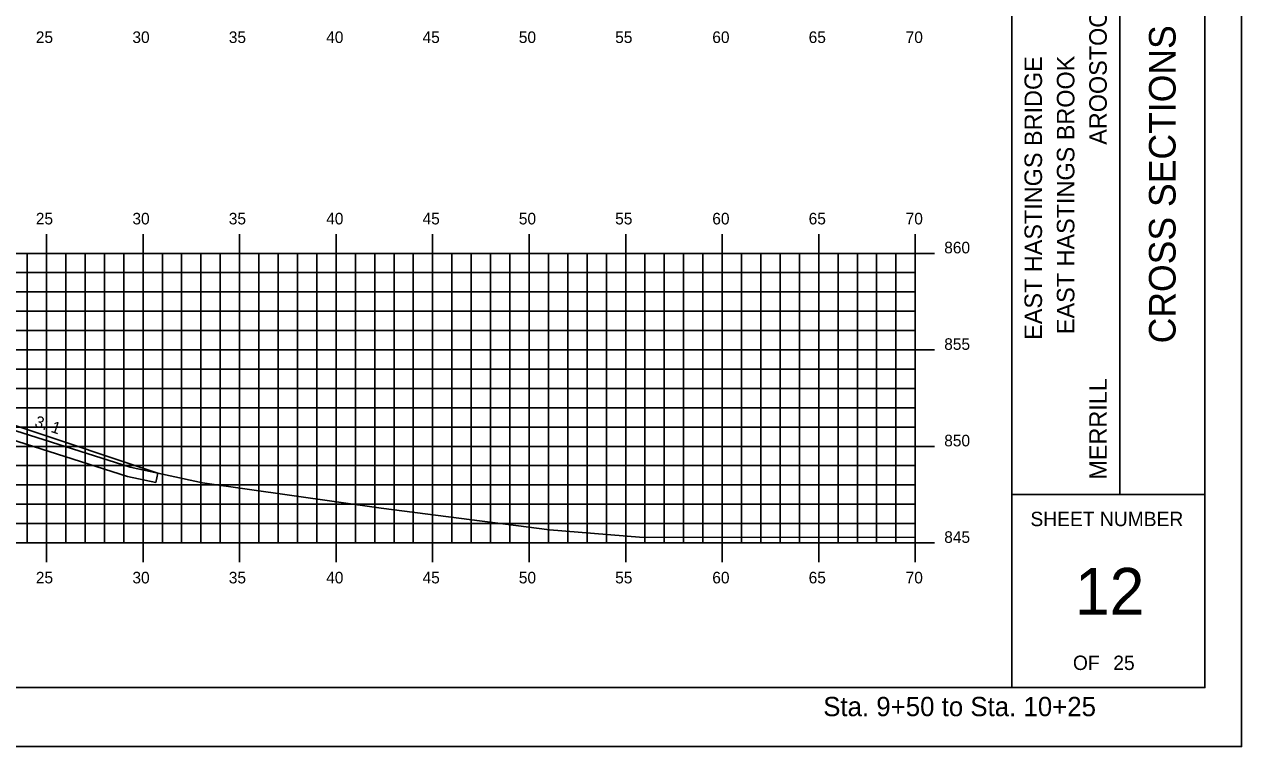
# Model space of a CAD drawing. Extents: x 2194738 to 2195190, y 863888 to 863998.
# Drawn here: x 2194944.1 to 2195007.2, y 863888.4 to 863925.8 of the extents above; entities that cross this region are included whole.
import ezdxf

# ---------------------------------------------------------------- set-up
doc = ezdxf.new("R2010")
doc.units = 0
for name, color, linetype in [('ANNOTATION', 7, 'Continuous'), ('BORDER', 7, 'Continuous'), ('BRIDGE_TITLE', 7, 'Continuous'), ('H_V ANNOTATION', 7, 'Continuous'), ('MAJOR', 7, 'Continuous'), ('MINOR', 7, 'Continuous'), ('PLOT BOUNDARY', 7, 'Continuous'), ('S_Roadway_Centerline', 7, 'Continuous'), ('TEMPLATE', 7, 'Continuous')]:
    doc.layers.add(name, color=color, linetype=linetype)

msp = doc.modelspace()

# ---------------------------------------------------------------- linework, layer by layer
at = {"layer": 'BORDER'}
for p, q in [((2194995.256, 863891.446), (2194995.256, 863996.446)), ((2195000.847, 863901.449), (2195000.847, 863936.449)), ((2194995.256, 863901.449), (2195005.256, 863901.449))]:
    msp.add_line(p, q, dxfattribs=at)
msp.add_lwpolyline([(2194845.256, 863891.446), (2195005.256, 863891.446), (2195005.256, 863996.446), (2194845.256, 863996.446)], close=True, dxfattribs=at)
at = {"layer": 'MAJOR'}
for p, q in [((2194945.256, 863914.948), (2194945.256, 863913.946)), ((2194950.256, 863914.948), (2194950.256, 863913.946)), ((2194955.256, 863914.948), (2194955.256, 863913.946)), ((2194960.256, 863914.948), (2194960.256, 863913.946)), ((2194965.256, 863914.948), (2194965.256, 863913.946)), ((2194970.256, 863914.948), (2194970.256, 863913.946)), ((2194975.256, 863914.948), (2194975.256, 863913.946)), ((2194980.256, 863914.948), (2194980.256, 863913.946)), ((2194985.256, 863914.948), (2194985.256, 863913.946)), ((2194990.256, 863914.948), (2194990.256, 863913.946)), ((2194850.256, 863913.946), (2194990.256, 863913.946)), ((2194850.256, 863913.946), (2194990.256, 863913.946)), ((2194945.256, 863898.946), (2194945.256, 863913.946)), ((2194950.256, 863898.946), (2194950.256, 863913.946)), ((2194955.256, 863898.946), (2194955.256, 863913.946)), ((2194960.256, 863898.946), (2194960.256, 863913.946)), ((2194965.256, 863898.946), (2194965.256, 863913.946)), ((2194970.256, 863898.946), (2194970.256, 863913.946)), ((2194975.256, 863898.946), (2194975.256, 863913.946)), ((2194980.256, 863898.946), (2194980.256, 863913.946)), ((2194985.256, 863898.946), (2194985.256, 863913.946)), ((2194991.258, 863913.946), (2194989.254, 863913.946)), ((2194990.256, 863898.946), (2194990.256, 863913.946)), ((2194990.256, 863898.946), (2194990.256, 863913.946)), ((2194850.256, 863908.946), (2194990.256, 863908.946)), ((2194991.258, 863908.946), (2194989.254, 863908.946)), ((2194850.256, 863903.946), (2194990.256, 863903.946)), ((2194991.258, 863903.946), (2194989.254, 863903.946)), ((2194850.256, 863898.946), (2194990.256, 863898.946)), ((2194945.256, 863897.944), (2194945.256, 863898.946)), ((2194950.256, 863897.944), (2194950.256, 863898.946)), ((2194955.256, 863897.944), (2194955.256, 863898.946)), ((2194960.256, 863897.944), (2194960.256, 863898.946)), ((2194965.256, 863897.944), (2194965.256, 863898.946)), ((2194970.256, 863897.944), (2194970.256, 863898.946)), ((2194975.256, 863897.944), (2194975.256, 863898.946)), ((2194980.256, 863897.944), (2194980.256, 863898.946)), ((2194985.256, 863897.944), (2194985.256, 863898.946)), ((2194991.258, 863898.946), (2194989.254, 863898.946)), ((2194990.256, 863897.944), (2194990.256, 863898.946))]:
    msp.add_line(p, q, dxfattribs=at)
at = {"layer": 'MINOR'}
for p, q in [((2194944.256, 863898.946), (2194944.256, 863913.946)), ((2194946.256, 863898.946), (2194946.256, 863913.946)), ((2194947.256, 863898.946), (2194947.256, 863913.946)), ((2194948.256, 863898.946), (2194948.256, 863913.946)), ((2194949.256, 863898.946), (2194949.256, 863913.946)), ((2194951.256, 863898.946), (2194951.256, 863913.946)), ((2194952.256, 863898.946), (2194952.256, 863913.946)), ((2194953.256, 863898.946), (2194953.256, 863913.946)), ((2194954.256, 863898.946), (2194954.256, 863913.946)), ((2194956.256, 863898.946), (2194956.256, 863913.946)), ((2194957.256, 863898.946), (2194957.256, 863913.946)), ((2194958.256, 863898.946), (2194958.256, 863913.946)), ((2194959.256, 863898.946), (2194959.256, 863913.946)), ((2194961.256, 863898.946), (2194961.256, 863913.946)), ((2194962.256, 863898.946), (2194962.256, 863913.946)), ((2194963.256, 863898.946), (2194963.256, 863913.946)), ((2194964.256, 863898.946), (2194964.256, 863913.946)), ((2194966.256, 863898.946), (2194966.256, 863913.946)), ((2194967.256, 863898.946), (2194967.256, 863913.946)), ((2194968.256, 863898.946), (2194968.256, 863913.946)), ((2194969.256, 863898.946), (2194969.256, 863913.946)), ((2194971.256, 863898.946), (2194971.256, 863913.946)), ((2194972.256, 863898.946), (2194972.256, 863913.946)), ((2194973.256, 863898.946), (2194973.256, 863913.946)), ((2194974.256, 863898.946), (2194974.256, 863913.946)), ((2194976.256, 863898.946), (2194976.256, 863913.946)), ((2194977.256, 863898.946), (2194977.256, 863913.946)), ((2194978.256, 863898.946), (2194978.256, 863913.946)), ((2194979.256, 863898.946), (2194979.256, 863913.946)), ((2194981.256, 863898.946), (2194981.256, 863913.946)), ((2194982.256, 863898.946), (2194982.256, 863913.946)), ((2194983.256, 863898.946), (2194983.256, 863913.946)), ((2194984.256, 863898.946), (2194984.256, 863913.946)), ((2194986.256, 863898.946), (2194986.256, 863913.946)), ((2194987.256, 863898.946), (2194987.256, 863913.946)), ((2194988.256, 863898.946), (2194988.256, 863913.946)), ((2194989.256, 863898.946), (2194989.256, 863913.946)), ((2194850.256, 863912.946), (2194990.256, 863912.946)), ((2194990.256, 863912.946), (2194989.254, 863912.946)), ((2194850.256, 863911.946), (2194990.256, 863911.946)), ((2194990.256, 863911.946), (2194989.254, 863911.946)), ((2194850.256, 863910.946), (2194990.256, 863910.946)), ((2194990.256, 863910.946), (2194989.254, 863910.946)), ((2194850.256, 863909.946), (2194990.256, 863909.946)), ((2194990.256, 863909.946), (2194989.254, 863909.946)), ((2194850.256, 863907.946), (2194990.256, 863907.946)), ((2194990.256, 863907.946), (2194989.254, 863907.946)), ((2194850.256, 863906.946), (2194990.256, 863906.946)), ((2194990.256, 863906.946), (2194989.254, 863906.946)), ((2194850.256, 863905.946), (2194990.256, 863905.946)), ((2194990.256, 863905.946), (2194989.254, 863905.946)), ((2194850.256, 863904.946), (2194990.256, 863904.946)), ((2194990.256, 863904.946), (2194989.254, 863904.946)), ((2194850.256, 863902.946), (2194990.256, 863902.946)), ((2194990.256, 863902.946), (2194989.254, 863902.946)), ((2194850.256, 863901.946), (2194990.256, 863901.946)), ((2194990.256, 863901.946), (2194989.254, 863901.946)), ((2194850.256, 863900.946), (2194990.256, 863900.946)), ((2194990.256, 863900.946), (2194989.254, 863900.946)), ((2194850.256, 863899.946), (2194990.256, 863899.946)), ((2194990.256, 863899.946), (2194989.254, 863899.946))]:
    msp.add_line(p, q, dxfattribs=at)
at = {"layer": 'PLOT BOUNDARY'}
msp.add_lwpolyline([(2194837.163, 863888.387), (2195007.163, 863888.387), (2195007.163, 863998.387), (2194837.163, 863998.387)], close=True, dxfattribs=at)
at = {"layer": 'S_Roadway_Centerline'}
msp.add_lwpolyline([(2194850.256, 863903.946), (2194862.163, 863904.928), (2194876.641, 863904.659), (2194888.683, 863904.484), (2194891.949, 863905.503), (2194896.37, 863906.93), (2194900.004, 863907.039), (2194904.289, 863907.129), (2194905.874, 863907.236), (2194908.794, 863907.591), (2194913.318, 863907.695), (2194920.296, 863907.807), (2194927.306, 863907.711), (2194931.88, 863907.66), (2194933.306, 863907.572), (2194934.219, 863907.522), (2194935.131, 863907.329), (2194936.586, 863906.993), (2194949.583, 863902.874), (2194953.328, 863902.06), (2194962.598, 863900.741), (2194971.313, 863899.617), (2194975.97, 863899.247), (2194990.256, 863899.22)], dxfattribs=at)
at = {"layer": 'TEMPLATE'}
msp.add_line((2194951.028, 863902.56), (2194950.921, 863902.072), dxfattribs=at)
for points in [[(2194936.586, 863907.374), (2194951.028, 863902.56)], [(2194941.316, 863904.97), (2194949.454, 863902.391), (2194950.921, 863902.072)]]:
    msp.add_lwpolyline(points, dxfattribs=at)

# ---------------------------------------------------------------- texts
at = {"layer": 'ANNOTATION'}
msp.add_text('3: 1', height=0.6, rotation=341.56505, dxfattribs=at).set_placement((2194944.596, 863904.986))
at = {"layer": 'BORDER'}
for s, height, rotation, p in [('CROSS SECTIONS', 1.37787, 90, (2195003.741, 863909.283)), ('SHEET NUMBER', 0.74527, 360, (2194996.221, 863899.812)), ('12', 2.4194, 360, (2194998.527, 863895.228)), ('OF', 0.7453, 360, (2194998.423, 863892.359)), ('25', 0.7453, 360, (2195000.513, 863892.359))]:
    msp.add_text(s, height=height, rotation=rotation, dxfattribs=at).set_placement(p)
at = {"layer": 'BRIDGE_TITLE'}
for s, height, p in [('AROOSTOOK COUNTY', 0.90716, (2195000.176, 863919.571)), ('EAST HASTINGS BRIDGE', 0.90716, (2194996.822, 863909.466)), ('EAST HASTINGS BROOK', 0.90716, (2194998.499, 863909.763)), ('MERRILL', 0.9072, (2195000.176, 863902.222))]:
    msp.add_text(s, height=height, rotation=90, dxfattribs=at).set_placement(p)
at = {"layer": 'H_V ANNOTATION'}
for s, height, p in [('25', 0.6, (2194944.702, 863924.846)), ('30', 0.6, (2194949.705, 863924.846)), ('35', 0.6, (2194954.697, 863924.846)), ('40', 0.6, (2194959.742, 863924.846)), ('45', 0.6, (2194964.734, 863924.846)), ('50', 0.6, (2194969.721, 863924.846)), ('55', 0.6, (2194974.712, 863924.846)), ('60', 0.6, (2194979.742, 863924.846)), ('65', 0.6, (2194984.734, 863924.846)), ('70', 0.6, (2194989.758, 863924.846)), ('25', 0.6, (2194944.702, 863915.446)), ('30', 0.6, (2194949.705, 863915.446)), ('35', 0.6, (2194954.697, 863915.446)), ('40', 0.6, (2194959.742, 863915.446)), ('45', 0.6, (2194964.734, 863915.446)), ('50', 0.6, (2194969.721, 863915.446)), ('55', 0.6, (2194974.712, 863915.446)), ('60', 0.6, (2194979.742, 863915.446)), ('65', 0.6, (2194984.734, 863915.446)), ('70', 0.6, (2194989.758, 863915.446)), ('860', 0.6, (2194991.756, 863913.946)), ('855', 0.6, (2194991.756, 863908.946)), ('850', 0.6, (2194991.756, 863903.946)), ('845', 0.6, (2194991.756, 863898.946)), ('25', 0.6, (2194944.702, 863896.846)), ('30', 0.6, (2194949.705, 863896.846)), ('35', 0.6, (2194954.697, 863896.846)), ('40', 0.6, (2194959.742, 863896.846)), ('45', 0.6, (2194964.734, 863896.846)), ('50', 0.6, (2194969.721, 863896.846)), ('55', 0.6, (2194974.712, 863896.846)), ('60', 0.6, (2194979.742, 863896.846)), ('65', 0.6, (2194984.734, 863896.846)), ('70', 0.6, (2194989.758, 863896.846)), ('Sta. 9+50 to Sta. 10+25', 1.0002, (2194985.488, 863889.966))]:
    msp.add_text(s, height=height, dxfattribs=at).set_placement(p)

doc.saveas('drawing.dxf')
